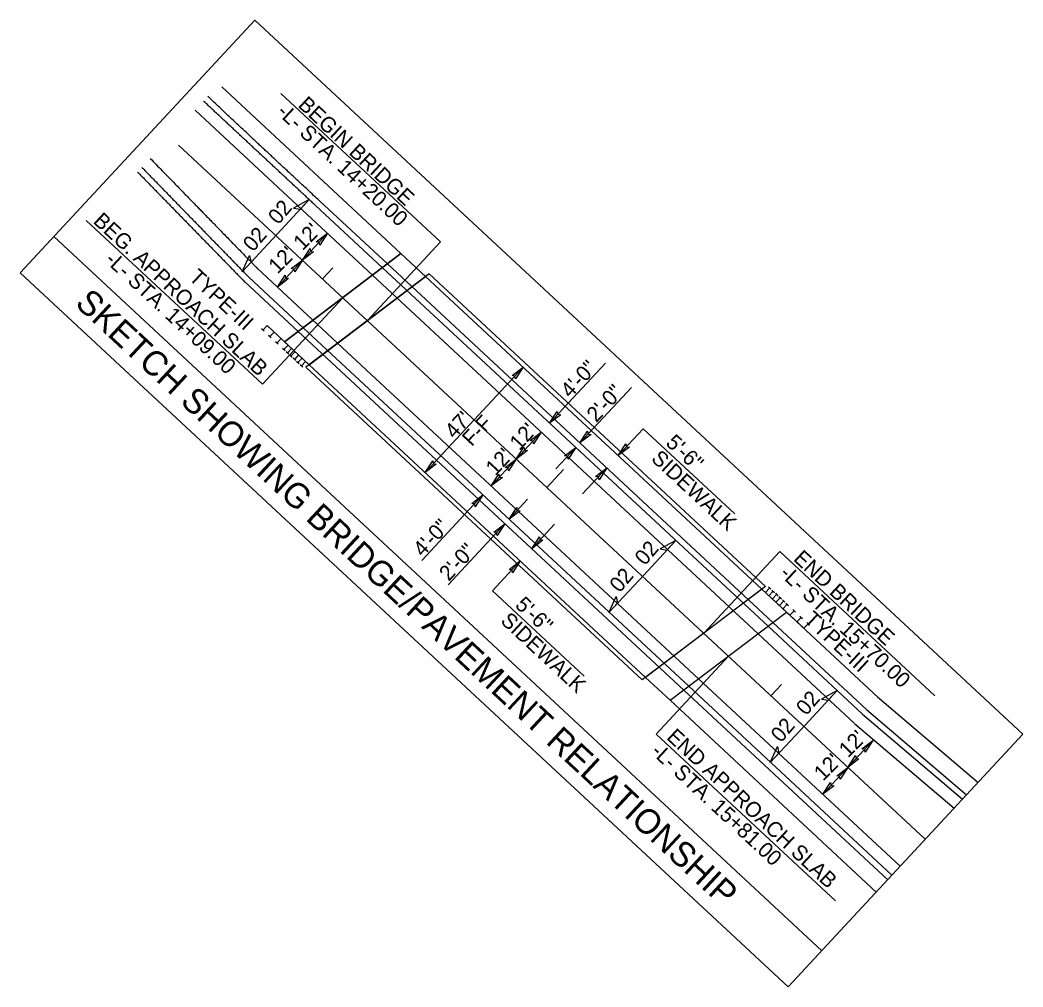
# Model space of a CAD drawing. Extents: x 2057696 to 2061410, y 685900 to 689434.
# Drawn here: x 2061082.7 to 2061410.4, y 687120.8 to 687436.6 of the extents above; entities that cross this region are included whole.
import ezdxf

# ---------------------------------------------------------------- set-up
doc = ezdxf.new("R2010")
doc.units = 0
for name, color, linetype in [('Old_Level_1', 7, 'Continuous'), ('Old_Level_63', 7, 'Continuous'), ('Prop Approach Slab', 7, 'Continuous'), ('Prop Boundary Buffer Zone 1', 7, 'Continuous'), ('Prop Guardrail', 7, 'Continuous'), ('Prop Hydrographic FEMA Cross Section', 7, 'Continuous'), ('Prop Structure Anchor Unit CELL', 7, 'Continuous'), ('Prop Vertical Profile Grade', 7, 'Continuous'), ('Prop Vertical Profile Grade Label', 7, 'Continuous'), ('Prop VPI Label', 7, 'Continuous'), ('Sheet Block Revision CELL', 7, 'Continuous'), ('Sheet Data Field CELL', 7, 'Continuous'), ('Sheet DOT Grid CELL', 7, 'Continuous'), ('Sheet Profile CELL', 7, 'Continuous'), ('Sheet Profile Grid Minor CELL', 7, 'Continuous'), ('Sheet Sticker Incomplete CELL', 7, 'Continuous')]:
    doc.layers.add(name, color=color, linetype=linetype)

msp = doc.modelspace()

# ---------------------------------------------------------------- linework, layer by layer
at = {"layer": 'Old_Level_1'}
for p, q in [((2061181.54, 687352.02), (2061184.94, 687355.68)), ((2061328.03, 687215.86), (2061331.43, 687219.52))]:
    msp.add_line(p, q, dxfattribs=at)
at = {"layer": 'Old_Level_63'}
for p, q in [((2061148.59, 687414.73), (2061207.16, 687360.29)), ((2061202.71, 687356.92), (2061328.69, 687239.82)), ((2061173.55, 687334.87), (2061299.54, 687217.77)), ((2061330.11, 687246.01), (2061363.07, 687215.37)), ((2061295.08, 687214.4), (2061362.44, 687151.79)), ((2061362.87, 687215.56), (2061395.7, 687187.58))]:
    msp.add_line(p, q, dxfattribs=at)
at = {"layer": 'Prop Approach Slab'}
for p, q in [((2061093.73, 687365.85), (2061344.64, 687132.64)), ((2061166.79, 687349.35), (2061183.13, 687366.93)), ((2061345, 687183.72), (2061361.33, 687201.29))]:
    msp.add_line(p, q, dxfattribs=at)
msp.add_lwpolyline([(2061333.63, 687120.8), (2061082.72, 687354.01), (2061159.45, 687436.56), (2061410.35, 687203.34)], close=True, dxfattribs=at)
at = {"layer": 'Prop Boundary Buffer Zone 1'}
for points in [[(2061179.5, 687364.16), (2061183.13, 687366.93), (2061180.64, 687363.07), (2061180.44, 687364.03)], [(2061178.59, 687360.91), (2061174.96, 687358.14), (2061177.45, 687362), (2061177.65, 687361.03)], [(2061171.33, 687355.37), (2061174.96, 687358.14), (2061172.46, 687354.28), (2061172.27, 687355.24)], [(2061170.42, 687352.12), (2061166.79, 687349.35), (2061169.29, 687353.21), (2061169.48, 687352.24)], [(2061243.44, 687320.43), (2061247.07, 687323.19), (2061244.58, 687319.34), (2061244.38, 687320.3)], [(2061259.36, 687307.67), (2061255.73, 687304.91), (2061258.23, 687308.76), (2061258.42, 687307.8)], [(2061249.38, 687299.21), (2061253.01, 687301.98), (2061250.51, 687298.12), (2061250.32, 687299.08)], [(2061269.25, 687301.21), (2061265.62, 687298.45), (2061268.11, 687302.3), (2061268.31, 687301.34)], [(2061248.47, 687295.95), (2061244.84, 687293.19), (2061247.33, 687297.05), (2061247.53, 687296.08)], [(2061260.63, 687294.21), (2061264.26, 687296.98), (2061261.76, 687293.12), (2061261.57, 687294.09)], [(2061281.77, 687297.09), (2061278.13, 687294.32), (2061280.63, 687298.18), (2061280.82, 687297.22)], [(2061218.7, 687291.54), (2061215.07, 687288.77), (2061217.57, 687292.63), (2061217.76, 687291.66)], [(2061241.21, 687290.42), (2061244.84, 687293.19), (2061242.34, 687289.33), (2061242.15, 687290.29)], [(2061270.76, 687287.53), (2061274.39, 687290.29), (2061271.89, 687286.43), (2061271.7, 687287.4)], [(2061240.3, 687287.17), (2061236.67, 687284.4), (2061239.16, 687288.26), (2061239.36, 687287.29)], [(2061230.31, 687278.7), (2061233.94, 687281.47), (2061231.45, 687277.61), (2061231.26, 687278.57)], [(2061246.1, 687276.31), (2061242.47, 687273.54), (2061244.97, 687277.4), (2061245.16, 687276.43)], [(2061237.48, 687269.31), (2061241.11, 687272.08), (2061238.62, 687268.22), (2061238.42, 687269.18)], [(2061253.51, 687266.69), (2061249.88, 687263.92), (2061252.38, 687267.78), (2061252.57, 687266.82)], [(2061242.5, 687257.13), (2061246.14, 687259.9), (2061243.64, 687256.04), (2061243.45, 687257)], [(2061357.7, 687198.52), (2061361.33, 687201.29), (2061358.84, 687197.43), (2061358.64, 687198.4)], [(2061356.79, 687195.27), (2061353.16, 687192.5), (2061355.66, 687196.36), (2061355.85, 687195.4)], [(2061349.53, 687189.73), (2061353.16, 687192.5), (2061350.67, 687188.64), (2061350.47, 687189.61)], [(2061348.63, 687186.48), (2061345, 687183.72), (2061347.49, 687187.57), (2061347.69, 687186.61)]]:
    msp.add_lwpolyline(points, close=True, dxfattribs=at)
at = {"layer": 'Prop Guardrail'}
msp.add_line((2061134.52, 687395.73), (2061378.44, 687169.01), dxfattribs=at)
at = {"layer": 'Prop Hydrographic FEMA Cross Section'}
for p, q in [((2061216.33, 687353.64), (2061176.11, 687323.22)), ((2061215.22, 687352.8), (2061325.09, 687250.68)), ((2061216.33, 687353.64), (2061326.2, 687251.52)), ((2061176.11, 687323.22), (2061285.98, 687221.1)), ((2061177.15, 687324.01), (2061287.02, 687221.89)), ((2061326.2, 687251.52), (2061285.98, 687221.1))]:
    msp.add_line(p, q, dxfattribs=at)
at = {"layer": 'Prop Structure Anchor Unit CELL'}
for p, q in [((2061169.1, 687331.5), (2061207.16, 687360.29)), ((2061295.08, 687214.4), (2061333.15, 687243.19))]:
    msp.add_line(p, q, dxfattribs=at)
at = {"layer": 'Prop Vertical Profile Grade'}
for p, q in [((2061176.52, 687373.07), (2061139.9, 687407.11)), ((2061176.52, 687373.07), (2061197.85, 687353.24)), ((2061160.18, 687355.49), (2061186.47, 687331.06)), ((2061197.85, 687353.24), (2061323.83, 687236.15)), ((2061186.47, 687331.06), (2061304.39, 687221.45)), ((2061323.83, 687236.15), (2061355.24, 687206.95)), ((2061304.39, 687221.45), (2061370.27, 687160.22)), ((2061355.37, 687206.83), (2061387.86, 687179.15))]:
    msp.add_line(p, q, dxfattribs=at)
msp.add_open_spline([(2061125.26, 687391.36), (2061137.05, 687379.26), (2061148.69, 687367.3), (2061160.33, 687355.35)], degree=2, dxfattribs=at)
at = {"layer": 'Prop Vertical Profile Grade Label'}
for p, q in [((2061162.48, 687334.92), (2061161.64, 687335.7)), ((2061163.42, 687336.78), (2061162.06, 687335.31)), ((2061177.15, 687324.01), (2061163.42, 687336.78)), ((2061165.71, 687334.65), (2061164.35, 687333.19)), ((2061164.77, 687332.8), (2061163.93, 687333.58)), ((2061167.06, 687330.67), (2061166.22, 687331.45)), ((2061168, 687332.52), (2061166.64, 687331.06)), ((2061169.34, 687328.54), (2061168.51, 687329.32)), ((2061170.29, 687330.4), (2061168.93, 687328.93)), ((2061170.49, 687327.48), (2061169.65, 687328.26)), ((2061171.43, 687329.33), (2061170.07, 687327.87)), ((2061172.58, 687328.27), (2061171.21, 687326.8)), ((2061171.63, 687326.41), (2061170.79, 687327.19)), ((2061172.78, 687325.35), (2061171.94, 687326.13)), ((2061173.72, 687327.2), (2061172.36, 687325.74)), ((2061173.92, 687324.29), (2061173.08, 687325.07)), ((2061174.86, 687326.14), (2061173.5, 687324.68)), ((2061176.01, 687325.08), (2061174.65, 687323.61)), ((2061175.07, 687323.22), (2061174.23, 687324)), ((2061325.09, 687250.68), (2061338.82, 687237.91)), ((2061326.24, 687249.61), (2061327.6, 687251.08)), ((2061327.18, 687251.47), (2061328.02, 687250.69)), ((2061327.38, 687248.55), (2061328.74, 687250.01)), ((2061328.32, 687250.4), (2061329.16, 687249.62)), ((2061329.47, 687249.34), (2061330.31, 687248.56)), ((2061328.52, 687247.49), (2061329.89, 687248.95)), ((2061329.67, 687246.42), (2061331.03, 687247.89)), ((2061330.61, 687248.28), (2061331.45, 687247.5)), ((2061330.81, 687245.36), (2061332.17, 687246.82)), ((2061331.76, 687247.21), (2061332.59, 687246.43)), ((2061332.9, 687246.15), (2061333.74, 687245.37)), ((2061331.96, 687244.29), (2061333.32, 687245.76)), ((2061334.25, 687242.17), (2061335.61, 687243.63)), ((2061335.19, 687244.02), (2061336.03, 687243.24)), ((2061336.54, 687240.04), (2061337.9, 687241.5)), ((2061337.48, 687241.89), (2061338.32, 687241.11)), ((2061339.77, 687239.77), (2061340.61, 687238.99)), ((2061338.82, 687237.91), (2061340.19, 687239.38))]:
    msp.add_line(p, q, dxfattribs=at)
at = {"layer": 'Prop VPI Label'}
for p, q in [((2061180.61, 687377.46), (2061202.71, 687356.92)), ((2061156.1, 687351.09), (2061173.55, 687334.87)), ((2061328.69, 687239.82), (2061359.3, 687211.37)), ((2061299.54, 687217.77), (2061366.19, 687155.82)), ((2061359.3, 687211.37), (2061391.95, 687183.54))]:
    msp.add_line(p, q, dxfattribs=at)
msp.add_open_spline([(2061180.61, 687377.46), (2061168.42, 687388.82), (2061156.22, 687400.18), (2061144.08, 687411.61)], degree=2, dxfattribs=at)
msp.add_spline([(2061121.13, 687386.92), (2061121.61, 687386.43), (2061122.08, 687385.95), (2061122.55, 687385.46), (2061123.02, 687384.98), (2061123.5, 687384.5), (2061123.97, 687384.01), (2061124.44, 687383.53), (2061124.91, 687383.04), (2061125.39, 687382.56), (2061125.86, 687382.07), (2061126.33, 687381.59), (2061126.8, 687381.11), (2061127.28, 687380.62), (2061127.75, 687380.14), (2061128.22, 687379.65), (2061128.69, 687379.17), (2061129.17, 687378.69), (2061129.64, 687378.2), (2061130.11, 687377.72), (2061130.58, 687377.23), (2061131.06, 687376.75), (2061131.53, 687376.27), (2061132, 687375.78), (2061132.47, 687375.3), (2061132.95, 687374.81), (2061133.42, 687374.33), (2061133.89, 687373.85), (2061134.36, 687373.36), (2061134.84, 687372.88), (2061135.31, 687372.39), (2061135.78, 687371.91), (2061136.25, 687371.42), (2061136.73, 687370.94), (2061137.2, 687370.46), (2061137.67, 687369.97), (2061138.14, 687369.49), (2061138.62, 687369), (2061139.09, 687368.52), (2061139.56, 687368.04), (2061140.03, 687367.55), (2061140.51, 687367.07), (2061140.98, 687366.58), (2061141.45, 687366.1), (2061141.92, 687365.62), (2061142.4, 687365.13), (2061142.87, 687364.65), (2061143.34, 687364.16), (2061143.81, 687363.68), (2061144.29, 687363.19), (2061144.76, 687362.71), (2061145.23, 687362.23), (2061145.7, 687361.74), (2061146.18, 687361.26), (2061146.65, 687360.77), (2061147.12, 687360.29), (2061147.59, 687359.81), (2061148.07, 687359.32), (2061148.54, 687358.84), (2061149.01, 687358.35), (2061149.48, 687357.87), (2061149.96, 687357.39), (2061150.43, 687356.9), (2061150.9, 687356.42), (2061151.37, 687355.93), (2061151.85, 687355.45), (2061152.32, 687354.96), (2061152.79, 687354.48), (2061153.26, 687354), (2061153.74, 687353.51), (2061154.21, 687353.03), (2061154.68, 687352.54), (2061155.15, 687352.06), (2061156.1, 687351.09)], degree=3, dxfattribs=at)
at = {"layer": 'Sheet Block Revision CELL'}
for p, q in [((2061220.07, 687364.11), (2061167.96, 687412.55)), ((2061161.9, 687317.67), (2061104.36, 687371.15)), ((2061196.19, 687338.41), (2061220.07, 687364.11)), ((2061188.13, 687345.89), (2061161.9, 687317.67)), ((2061215.07, 687288.77), (2061247.07, 687323.19)), ((2061255.73, 687304.91), (2061273.96, 687324.52)), ((2061265.62, 687298.45), (2061282.49, 687316.6)), ((2061244.84, 687293.19), (2061253.01, 687301.98)), ((2061278.13, 687294.32), (2061286.29, 687303.1)), ((2061286.29, 687303.1), (2061316.25, 687275.26)), ((2061257.75, 687289.98), (2061264.26, 687296.98)), ((2061236.67, 687284.4), (2061244.84, 687293.19)), ((2061266.52, 687281.83), (2061274.39, 687290.29)), ((2061214.01, 687260.02), (2061233.94, 687281.47)), ((2061242.47, 687273.54), (2061248.54, 687280.07)), ((2061222.54, 687252.09), (2061241.11, 687272.08)), ((2061249.88, 687263.92), (2061257.31, 687271.92)), ((2061306.06, 687236.29), (2061330.88, 687262.99)), ((2061330.88, 687262.99), (2061381.55, 687215.9)), ((2061237.08, 687250.15), (2061246.14, 687259.9)), ((2061237.08, 687250.15), (2061267.04, 687222.31)), ((2061314.11, 687228.8), (2061290.48, 687203.37)), ((2061290.48, 687203.37), (2061349.1, 687148.88))]:
    msp.add_line(p, q, dxfattribs=at)
at = {"layer": 'Sheet Data Field CELL'}
msp.add_line((2061254.78, 687283.94), (2061260.23, 687289.8), dxfattribs=at)
at = {"layer": 'Sheet DOT Grid CELL'}
for points in [[(2061215.22, 687352.8), (2061207.16, 687360.29), (2061169.1, 687331.5), (2061177.15, 687324.01)], [(2061287.03, 687221.89), (2061295.08, 687214.4), (2061333.15, 687243.19), (2061325.09, 687250.68)]]:
    msp.add_lwpolyline(points, close=True, dxfattribs=at)
at = {"layer": 'Sheet Profile Grid Minor CELL'}
for p, q in [((2061166.69, 687366.64), (2061177.18, 687377.92)), ((2061155.3, 687354.38), (2061166.69, 687366.64)), ((2061286.46, 687255.32), (2061296.95, 687266.6)), ((2061275.07, 687243.05), (2061286.46, 687255.32)), ((2061339.17, 687206.33), (2061349.65, 687217.61)), ((2061327.77, 687194.07), (2061339.17, 687206.33))]:
    msp.add_line(p, q, dxfattribs=at)
for points in [[(2061177.18, 687377.92), (2061172.09, 687375.14), (2061174.29, 687374.81)], [(2061155.3, 687354.38), (2061157.7, 687359.65), (2061158.18, 687357.48)], [(2061296.95, 687266.6), (2061291.86, 687263.82), (2061294.06, 687263.49)], [(2061275.07, 687243.05), (2061277.47, 687248.33), (2061277.95, 687246.16)], [(2061349.65, 687217.61), (2061344.56, 687214.83), (2061346.76, 687214.5)], [(2061327.77, 687194.07), (2061330.17, 687199.35), (2061330.66, 687197.17)]]:
    msp.add_lwpolyline(points, close=True, dxfattribs=at)
at = {"layer": 'Sheet Sticker Incomplete CELL'}
for p, q in [((2061179.25, 687376), (2061201.09, 687355.69)), ((2061201.09, 687355.69), (2061327.07, 687238.59)), ((2061157.46, 687352.56), (2061175.17, 687336.1)), ((2061175.17, 687336.1), (2061301.16, 687219)), ((2061327.07, 687238.59), (2061357.97, 687209.88)), ((2061301.16, 687219), (2061367.55, 687157.29)), ((2061357.97, 687209.88), (2061390.59, 687182.08))]:
    msp.add_line(p, q, dxfattribs=at)
for points in [[(2061179.25, 687376), (2061178.75, 687376.46), (2061178.26, 687376.92), (2061177.76, 687377.38), (2061177.27, 687377.84), (2061176.77, 687378.3), (2061176.28, 687378.76), (2061175.79, 687379.22), (2061175.29, 687379.68), (2061174.8, 687380.14), (2061174.3, 687380.6), (2061173.81, 687381.06), (2061173.31, 687381.52), (2061172.82, 687381.98), (2061172.33, 687382.44), (2061171.83, 687382.91), (2061171.34, 687383.37), (2061170.84, 687383.83), (2061170.35, 687384.29), (2061169.85, 687384.75), (2061169.36, 687385.21), (2061168.87, 687385.67), (2061168.37, 687386.13), (2061167.88, 687386.59), (2061167.38, 687387.05), (2061166.89, 687387.51), (2061166.39, 687387.97), (2061165.9, 687388.43), (2061165.41, 687388.89), (2061164.91, 687389.35), (2061164.42, 687389.81), (2061163.92, 687390.28), (2061163.43, 687390.74), (2061162.93, 687391.2), (2061162.44, 687391.66), (2061161.95, 687392.12), (2061161.45, 687392.58), (2061160.96, 687393.04), (2061160.46, 687393.5), (2061159.97, 687393.96), (2061159.47, 687394.42), (2061158.98, 687394.88), (2061158.48, 687395.34), (2061157.99, 687395.8), (2061157.5, 687396.26), (2061157, 687396.72), (2061156.51, 687397.19), (2061156.01, 687397.65), (2061155.52, 687398.11), (2061155.02, 687398.57), (2061154.53, 687399.03), (2061154.04, 687399.49), (2061153.54, 687399.95), (2061153.05, 687400.41), (2061152.55, 687400.87), (2061152.06, 687401.33), (2061151.56, 687401.79), (2061151.07, 687402.25), (2061150.58, 687402.71), (2061150.08, 687403.17), (2061149.59, 687403.63), (2061149.09, 687404.09), (2061148.6, 687404.56), (2061148.1, 687405.02), (2061147.61, 687405.48), (2061147.12, 687405.94), (2061146.62, 687406.4), (2061146.13, 687406.86), (2061145.63, 687407.32), (2061145.14, 687407.78), (2061144.64, 687408.24), (2061144.15, 687408.7), (2061143.66, 687409.16), (2061142.67, 687410.08)], [(2061122.54, 687388.43), (2061123.01, 687387.94), (2061123.48, 687387.46), (2061123.95, 687386.97), (2061124.43, 687386.49), (2061124.9, 687386), (2061125.37, 687385.52), (2061125.84, 687385.03), (2061126.31, 687384.55), (2061126.79, 687384.06), (2061127.26, 687383.58), (2061127.73, 687383.1), (2061128.2, 687382.61), (2061128.67, 687382.13), (2061129.15, 687381.64), (2061129.62, 687381.16), (2061130.09, 687380.67), (2061130.56, 687380.19), (2061131.03, 687379.7), (2061131.5, 687379.22), (2061131.98, 687378.73), (2061132.45, 687378.25), (2061132.92, 687377.76), (2061133.39, 687377.28), (2061133.86, 687376.79), (2061134.34, 687376.31), (2061134.81, 687375.82), (2061135.28, 687375.34), (2061135.75, 687374.85), (2061136.22, 687374.37), (2061136.7, 687373.89), (2061137.17, 687373.4), (2061137.64, 687372.92), (2061138.11, 687372.43), (2061138.58, 687371.95), (2061139.06, 687371.46), (2061139.53, 687370.98), (2061140, 687370.49), (2061140.47, 687370.01), (2061140.94, 687369.52), (2061141.42, 687369.04), (2061141.89, 687368.55), (2061142.36, 687368.07), (2061142.83, 687367.58), (2061143.3, 687367.1), (2061143.77, 687366.61), (2061144.25, 687366.13), (2061144.72, 687365.64), (2061145.19, 687365.16), (2061145.66, 687364.68), (2061146.13, 687364.19), (2061146.61, 687363.71), (2061147.08, 687363.22), (2061147.55, 687362.74), (2061148.02, 687362.25), (2061148.49, 687361.77), (2061148.97, 687361.28), (2061149.44, 687360.8), (2061149.91, 687360.31), (2061150.38, 687359.83), (2061150.85, 687359.34), (2061151.33, 687358.86), (2061151.8, 687358.37), (2061152.27, 687357.89), (2061152.74, 687357.4), (2061153.21, 687356.92), (2061153.69, 687356.43), (2061154.16, 687355.95), (2061154.63, 687355.47), (2061155.1, 687354.98), (2061155.57, 687354.5), (2061156.04, 687354.01), (2061156.52, 687353.53), (2061157.46, 687352.56)]]:
    msp.add_spline(points, degree=3, dxfattribs=at)

# ---------------------------------------------------------------- texts
at = {"layer": 'Prop Approach Slab'}
for p in [(2061175.02, 687361.05), (2061166.88, 687353.43), (2061353.23, 687195.41), (2061345.09, 687187.8)]:
    msp.add_text("12'", height=5, rotation=45.193, dxfattribs=at).set_placement(p)
at = {"layer": 'Sheet Block Revision CELL'}
for s, height, rotation, p in [('BEGIN BRIDGE', 5, 317.0934, (2061173.25, 687408.45)), ('-L- STA. 14+20.00', 5, 317.0934, (2061166.35, 687406.12)), ('BEG. APPROACH SLAB', 5, 317.0934, (2061106.32, 687370.51)), ('-L- STA. 14+09.00', 5, 317.0934, (2061110.18, 687357.82)), ('TYPE-III', 5, 317.0934, (2061137.61, 687352.06)), ('SKETCH SHOWING BRIDGE/PAVEMENT RELATIONSHIP', 8.1, 317.0934, (2061100.33, 687343.55)), ('4\'-0"', 5, 47.0934, (2061262.46, 687312.83)), ('2\'-0"', 5, 47.0934, (2061270.98, 687304.9)), ("47'", 5, 47.0934, (2061224.61, 687299.52)), ('F-F', 5, 47.0934, (2061230.3, 687297.03)), ("12'", 5, 47.0934, (2061245.82, 687295.71)), ('5\'-6"', 5, 317.0934, (2061293.37, 687298.05)), ("12'", 5, 47.0934, (2061238, 687287.49)), ('SIDEWALK', 5, 317.0934, (2061288.6, 687292.92)), ('4\'-0"', 5, 47.0934, (2061214.27, 687260.99)), ('2\'-0"', 5, 47.0934, (2061222.8, 687253.06)), ('END BRIDGE', 5, 317.0934, (2061335.08, 687260.27)), ('-L- STA. 15+70.00', 5, 317.0934, (2061330.54, 687255.39)), ('5\'-6"', 5, 317.0934, (2061244.15, 687245.1)), ('SIDEWALK', 5, 317.0934, (2061239.39, 687239.97)), ('TYPE-III', 5, 317.0934, (2061338.53, 687240.35)), ('END APPROACH SLAB', 5, 317.0934, (2061293.64, 687201.98)), ('-L- STA. 15+81.00', 5, 317.0934, (2061288.53, 687197.26))]:
    msp.add_text(s, height=height, rotation=rotation, dxfattribs=at).set_placement(p)
at = {"layer": 'Sheet Profile CELL'}
for p in [(2061167.08, 687369.47), (2061158.84, 687360.61), (2061286.85, 687258.15), (2061278.61, 687249.28), (2061339.55, 687209.16), (2061331.31, 687200.3)]:
    msp.add_text('02', height=5, rotation=49.3596, dxfattribs=at).set_placement(p)

doc.saveas('drawing.dxf')
